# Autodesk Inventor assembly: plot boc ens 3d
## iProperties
Author: ajt
Created: 2001-10
Part Number: plot boc ens 3d
Document SubType Name: Assemblage
Designer: ajt
Control State: 0
Master: False
Checked Out: False
PropertySet Name: Design Tracking Control
Shininess: 21.0
PropertySet Name: _Private Model Information
Length Units: 11269
Angle Units: 11283
Time Units: 11279
Mass Units: 11290
Length Display Precision: 3
Angle Display Precision: 2
Compacted: False
Density: 0.0
Volumn: 0.0
Area: 0.0
PropertySet Name: Model Information
